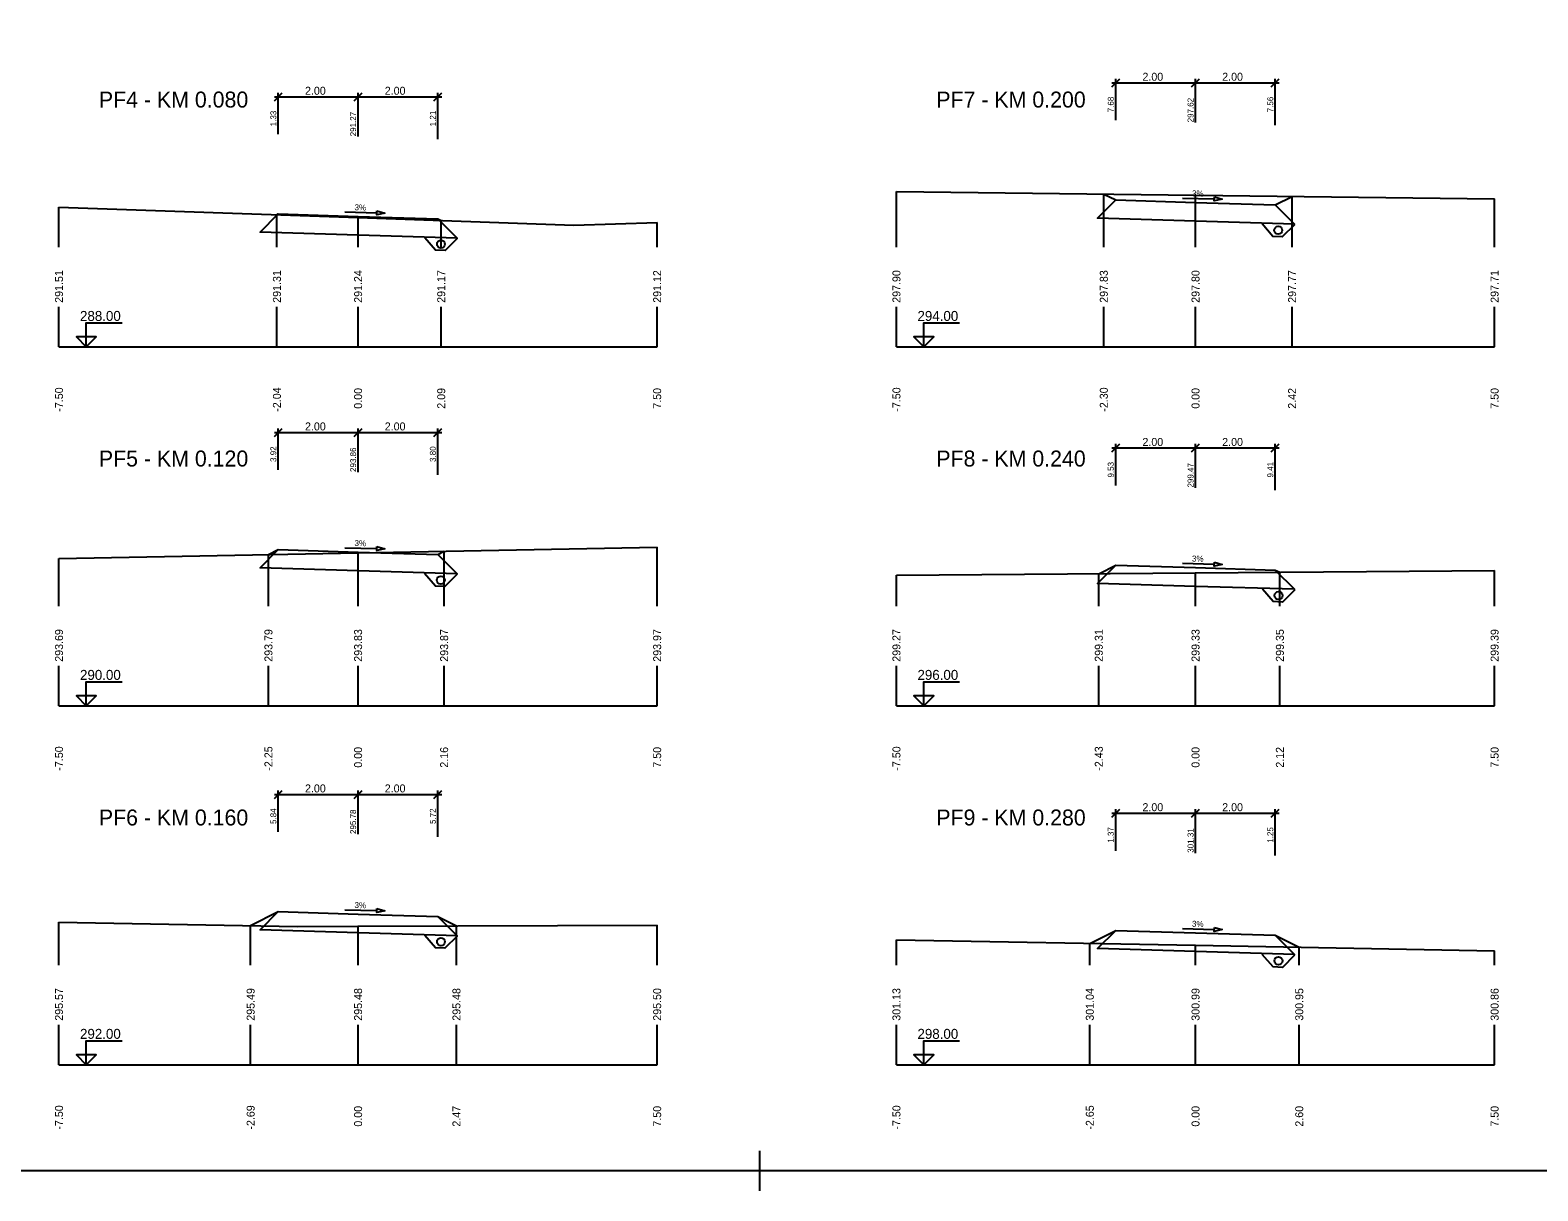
# Model space of a CAD drawing. Extents: x -9 to 2311, y -2 to 597.
# Drawn here: x 232.8 to 610.8, y -1.6 to 289.4 of the extents above; entities that cross this region are included whole.
import ezdxf

# ---------------------------------------------------------------- set-up
doc = ezdxf.new("R2010")
doc.units = 0
for name, color, linetype in [('KOTA', 7, 'Continuous'), ('KOTA_DELKY', 7, 'Continuous'), ('KOTA_DELKY_CONT', 7, 'Continuous'), ('NS_TELESO_VOZOVKY', 7, 'Continuous'), ('NS_V_PF', 7, 'Continuous'), ('REZY_PF_PUVODNI', 7, 'Continuous'), ('SESTAVY_REZU_PF', 7, 'Continuous'), ('SKLON', 7, 'Continuous'), ('SVK', 7, 'Continuous')]:
    doc.layers.add(name, color=color, linetype=linetype)

msp = doc.modelspace()

# ---------------------------------------------------------------- linework, layer by layer
for p, q in [((415.65, 8.39), (415.65, -1.61)), ((415.65, 8.39), (415.65, -1.61)), ((415.65, 8.39), (415.65, -1.61)), ((415.65, 8.39), (415.65, -1.61)), ((420.65, 3.39), (410.65, 3.39)), ((420.65, 3.39), (410.65, 3.39)), ((420.65, 3.39), (410.65, 3.39)), ((420.65, 3.39), (410.65, 3.39))]:
    msp.add_line(p, q)
msp.add_lwpolyline([(-4.35, 597.39), (2305.65, 597.39), (2305.65, 3.39), (-4.35, 3.39)], close=True)
for points in [[(549.79, 240.63), (546.74, 237.6), (544.39, 237.7), (541.68, 240.83)], [(339.85, 237.16), (336.8, 234.13), (334.45, 234.23), (331.74, 237.36)], [(339.8, 152.94), (336.75, 149.9), (334.4, 150), (331.69, 153.14)], [(549.87, 149.06), (546.82, 146.02), (544.47, 146.12), (541.76, 149.25)], [(339.85, 62.25), (336.79, 59.21), (334.45, 59.31), (331.74, 62.45)], [(549.85, 57.47), (546.8, 54.43), (544.45, 54.53), (541.74, 57.67)]]:
    msp.add_lwpolyline(points)
for centre in [(545.73, 239.23), (335.79, 235.76), (335.74, 151.53), (545.81, 147.65), (335.79, 60.84), (545.79, 56.07)]:
    msp.add_circle(centre, 1)
at = {"layer": 'KOTA'}
for points in [[(246.85, 212.5), (244.35, 212.5), (246.85, 210), (246.85, 216), (255.85, 216)], [(456.85, 212.5), (454.35, 212.5), (456.85, 210), (456.85, 216), (465.85, 216)], [(246.85, 210), (249.35, 212.5), (246.85, 212.5)], [(456.85, 210), (459.35, 212.5), (456.85, 212.5)], [(246.85, 122.5), (244.35, 122.5), (246.85, 120), (246.85, 126), (255.85, 126)], [(456.85, 122.5), (454.35, 122.5), (456.85, 120), (456.85, 126), (465.85, 126)], [(246.85, 120), (249.35, 122.5), (246.85, 122.5)], [(456.85, 120), (459.35, 122.5), (456.85, 122.5)], [(246.85, 32.5), (244.35, 32.5), (246.85, 30), (246.85, 36), (255.85, 36)], [(456.85, 32.5), (454.35, 32.5), (456.85, 30), (456.85, 36), (465.85, 36)], [(246.85, 30), (249.35, 32.5), (246.85, 32.5)], [(456.85, 30), (459.35, 32.5), (456.85, 32.5)]]:
    msp.add_lwpolyline(points, dxfattribs=at)
at = {"layer": 'KOTA_DELKY'}
for points in [[(504, 275.22), (506, 277.22)], [(504, 276.22), (526, 276.22)], [(505, 266.82), (505, 277.22)], [(524, 275.22), (526, 277.22)], [(524, 275.22), (526, 277.22)], [(524, 276.22), (546, 276.22)], [(525, 266.22), (525, 277.22)], [(525, 266.22), (525, 277.22)], [(544, 275.22), (546, 277.22)], [(545, 265.62), (545, 277.22)], [(294, 271.71), (296, 273.71)], [(294, 272.71), (316, 272.71)], [(295, 263.31), (295, 273.71)], [(314, 271.71), (316, 273.71)], [(314, 271.71), (316, 273.71)], [(314, 272.71), (336, 272.71)], [(315, 262.71), (315, 273.71)], [(315, 262.71), (315, 273.71)], [(334, 271.71), (336, 273.71)], [(335, 262.11), (335, 273.71)], [(294, 187.55), (296, 189.55)], [(295, 179.15), (295, 189.55)], [(314, 187.55), (316, 189.55)], [(314, 187.55), (316, 189.55)], [(315, 178.55), (315, 189.55)], [(315, 178.55), (315, 189.55)], [(334, 187.55), (336, 189.55)], [(335, 177.95), (335, 189.55)], [(294, 188.55), (316, 188.55)], [(314, 188.55), (336, 188.55)], [(504, 183.65), (506, 185.65)], [(505, 175.25), (505, 185.65)], [(524, 183.65), (526, 185.65)], [(524, 183.65), (526, 185.65)], [(525, 174.65), (525, 185.65)], [(525, 174.65), (525, 185.65)], [(544, 183.65), (546, 185.65)], [(545, 174.05), (545, 185.65)], [(504, 184.65), (526, 184.65)], [(524, 184.65), (546, 184.65)], [(294, 96.79), (296, 98.79)], [(295, 88.39), (295, 98.79)], [(314, 96.79), (316, 98.79)], [(314, 96.79), (316, 98.79)], [(315, 87.79), (315, 98.79)], [(315, 87.79), (315, 98.79)], [(334, 96.79), (336, 98.79)], [(335, 87.19), (335, 98.79)], [(294, 97.79), (316, 97.79)], [(314, 97.79), (336, 97.79)], [(504, 92.08), (506, 94.08)], [(504, 93.08), (526, 93.08)], [(505, 83.68), (505, 94.08)], [(524, 92.08), (526, 94.08)], [(524, 92.08), (526, 94.08)], [(524, 93.08), (546, 93.08)], [(525, 83.08), (525, 94.08)], [(525, 83.08), (525, 94.08)], [(544, 92.08), (546, 94.08)], [(545, 82.48), (545, 94.08)]]:
    msp.add_lwpolyline(points, dxfattribs=at)
at = {"layer": 'NS_TELESO_VOZOVKY'}
for points in [[(525, 246.22), (545, 245.62), (545, 245.62), (549.85, 240.77), (525, 241.52), (500.44, 242.25), (505, 246.82), (505, 246.82), (525, 246.22)], [(315, 242.71), (335, 242.11), (335, 242.11), (339.85, 237.26), (315, 238.01), (290.44, 238.75), (295, 243.31), (295, 243.31), (315, 242.71)], [(315, 158.55), (335, 157.95), (335, 157.95), (339.85, 153.11), (315, 153.85), (290.44, 154.59), (295, 159.15), (295, 159.15), (315, 158.55)], [(525, 154.65), (545, 154.05), (545, 154.05), (549.85, 149.21), (525, 149.95), (500.44, 150.69), (505, 155.25), (505, 155.25), (525, 154.65)], [(315, 67.79), (335, 67.19), (335, 67.19), (339.85, 62.34), (315, 63.09), (290.44, 63.82), (295, 68.39), (295, 68.39), (315, 67.79)], [(525, 63.08), (545, 62.48), (545, 62.48), (549.85, 57.64), (525, 58.38), (500.44, 59.12), (505, 63.68), (505, 63.68), (525, 63.08)]]:
    msp.add_lwpolyline(points, dxfattribs=at)
at = {"layer": 'NS_V_PF'}
for points in [[(502, 248.32), (505, 246.82), (505, 246.82), (525, 246.22), (545, 245.62), (545, 245.62), (549.21, 247.72)], [(294.65, 243.13), (295, 243.31), (295, 243.31), (315, 242.71), (335, 242.11), (335, 242.11), (335.85, 241.68)], [(292.52, 157.91), (295, 159.15), (295, 159.15), (315, 158.55), (335, 157.95), (335, 157.95), (336.58, 158.74)], [(500.74, 153.12), (505, 155.25), (505, 155.25), (525, 154.65), (545, 154.05), (545, 154.05), (546.15, 153.47)], [(288.06, 64.91), (295, 68.39), (295, 68.39), (315, 67.79), (335, 67.19), (335, 67.19), (339.67, 64.85)], [(498.49, 60.43), (505, 63.68), (505, 63.68), (525, 63.08), (545, 62.48), (545, 62.48), (551.01, 59.48)]]:
    msp.add_lwpolyline(points, dxfattribs=at)
at = {"layer": 'REZY_PF_PUVODNI'}
for points in [[(450, 248.97), (525, 248.03), (525, 248.03), (600, 247.08)], [(240, 245.05), (315, 242.41), (315, 242.41), (369.12, 240.51), (390, 241.16)], [(240, 156.92), (315, 158.33), (315, 158.33), (390, 159.74)], [(450, 152.73), (525, 153.31), (525, 153.31), (600, 153.89)], [(240, 65.75), (299.84, 64.71), (315, 64.76), (315, 64.76), (390, 65.02)], [(450, 61.3), (525, 59.95), (525, 59.95), (600, 58.59)]]:
    msp.add_lwpolyline(points, dxfattribs=at)
at = {"layer": 'SESTAVY_REZU_PF'}
for points in [[(240, 210), (390, 210)], [(450, 210), (600, 210)], [(240, 120), (390, 120)], [(450, 120), (600, 120)], [(240, 30), (390, 30)], [(450, 30), (600, 30)]]:
    msp.add_lwpolyline(points, dxfattribs=at)
at = {"layer": 'SKLON'}
for points in [[(521.71, 247.32), (529.71, 247.08)], [(529.73, 247.58), (531.71, 247.02), (529.7, 246.58), (529.73, 247.58)], [(311.71, 243.81), (319.71, 243.57)], [(319.73, 244.07), (321.71, 243.51), (319.7, 243.07), (319.73, 244.07)], [(311.71, 159.65), (319.71, 159.41)], [(319.73, 159.91), (321.71, 159.35), (319.7, 158.91), (319.73, 159.91)], [(521.71, 155.75), (529.71, 155.51)], [(529.73, 156.01), (531.71, 155.45), (529.7, 155.01), (529.73, 156.01)], [(311.71, 68.88), (319.71, 68.64)], [(319.73, 69.14), (321.71, 68.58), (319.7, 68.14), (319.73, 69.14)], [(529.73, 64.44), (531.71, 63.88), (529.7, 63.44), (529.73, 64.44)], [(521.71, 64.18), (529.71, 63.94)]]:
    msp.add_lwpolyline(points, dxfattribs=at)
at = {"layer": 'SVK'}
for points in [[(450, 235), (450, 248.97)], [(502, 235), (502, 248.32)], [(525, 235), (525, 248.03)], [(549.21, 235), (549.21, 247.72)], [(600, 235), (600, 247.08)], [(240, 235), (240, 245.05)], [(294.65, 235), (294.65, 243.13)], [(315, 235), (315, 242.41)], [(335.85, 235), (335.85, 241.68)], [(390, 235), (390, 241.16)], [(240, 210), (240, 220)], [(294.65, 210), (294.65, 220)], [(315, 210), (315, 220)], [(335.85, 210), (335.85, 220)], [(390, 210), (390, 220)], [(450, 210), (450, 220)], [(502, 210), (502, 220)], [(525, 210), (525, 220)], [(549.21, 210), (549.21, 220)], [(600, 210), (600, 220)], [(390, 145), (390, 159.74)], [(240, 145), (240, 156.92)], [(292.52, 145), (292.52, 157.91)], [(315, 145), (315, 158.33)], [(336.58, 145), (336.58, 158.74)], [(450, 145), (450, 152.73)], [(500.74, 145), (500.74, 153.12)], [(525, 145), (525, 153.31)], [(546.15, 145), (546.15, 153.47)], [(600, 145), (600, 153.89)], [(240, 120), (240, 130)], [(292.52, 120), (292.52, 130)], [(315, 120), (315, 130)], [(336.58, 120), (336.58, 130)], [(390, 120), (390, 130)], [(450, 120), (450, 130)], [(500.74, 120), (500.74, 130)], [(525, 120), (525, 130)], [(546.15, 120), (546.15, 130)], [(600, 120), (600, 130)], [(240, 55), (240, 65.75)], [(288.06, 55), (288.06, 64.91)], [(315, 55), (315, 64.76)], [(339.67, 55), (339.67, 64.85)], [(390, 55), (390, 65.02)], [(450, 55), (450, 61.3)], [(498.49, 55), (498.49, 60.43)], [(525, 55), (525, 59.95)], [(551.01, 55), (551.01, 59.48)], [(600, 55), (600, 58.59)], [(240, 30), (240, 40)], [(288.06, 30), (288.06, 40)], [(315, 30), (315, 40)], [(339.67, 30), (339.67, 40)], [(390, 30), (390, 40)], [(450, 30), (450, 40)], [(498.49, 30), (498.49, 40)], [(525, 30), (525, 40)], [(551.01, 30), (551.01, 40)], [(600, 30), (600, 40)]]:
    msp.add_lwpolyline(points, dxfattribs=at)

# ---------------------------------------------------------------- texts
at = {"layer": 'KOTA'}
for s, p in [('288.00', (245.27, 216.5)), ('294.00', (455.27, 216.5)), ('290.00', (245.27, 126.5)), ('296.00', (455.27, 126.5)), ('292.00', (245.27, 36.5)), ('298.00', (455.27, 36.5))]:
    msp.add_text(s, height=2.5, dxfattribs=at).set_placement(p)
at = {"layer": 'KOTA_DELKY'}
for p in [(511.69, 276.72), (531.69, 276.72), (301.69, 273.21), (321.69, 273.21), (301.69, 189.05), (321.69, 189.05), (511.69, 185.15), (531.69, 185.15), (301.69, 98.29), (321.69, 98.29), (511.69, 93.58), (531.69, 93.58)]:
    msp.add_text('2.00', height=2, dxfattribs=at).set_placement(p)
at = {"layer": 'KOTA_DELKY_CONT'}
for s, p in [('7.68', (504.5, 268.81)), ('297.62', (524.5, 266.29)), ('7.56', (544.5, 268.81)), ('1.33', (294.5, 265.3)), ('291.27', (314.5, 262.79)), ('1.21', (334.5, 265.3)), ('3.92', (294.5, 181.14)), ('293.86', (314.5, 178.63)), ('3.80', (334.5, 181.14)), ('9.53', (504.5, 177.24)), ('299.47', (524.5, 174.73)), ('9.41', (544.5, 177.24)), ('5.84', (294.5, 90.37)), ('295.78', (314.5, 87.86)), ('5.72', (334.5, 90.37)), ('1.37', (504.5, 85.67)), ('301.31', (524.5, 83.16)), ('1.25', (544.5, 85.67))]:
    msp.add_text(s, height=1.5, rotation=90, dxfattribs=at).set_placement(p)
at = {"layer": 'SESTAVY_REZU_PF'}
for s, p in [('PF4 - KM 0.080', (250, 270)), ('PF7 - KM 0.200', (460, 270)), ('PF5 - KM 0.120', (250, 180)), ('PF8 - KM 0.240', (460, 180)), ('PF6 - KM 0.160', (250, 90)), ('PF9 - KM 0.280', (460, 90))]:
    msp.add_text(s, height=4, dxfattribs=at).set_placement(p)
at = {"layer": 'SKLON'}
for p in [(314.09, 244.24), (524.09, 247.75), (314.09, 160.08), (524.09, 156.18), (314.09, 69.31), (524.09, 64.61)]:
    msp.add_text('3%', height=1.5, rotation=358.2816, dxfattribs=at).set_placement(p)
at = {"layer": 'SVK'}
for s, p in [(' 291.51', (241, 220.3)), (' 291.31', (295.65, 220.3)), (' 291.24', (316, 220.3)), (' 291.17', (336.85, 220.3)), (' 291.12', (391, 220.3)), (' 297.90', (451, 220.3)), (' 297.83', (503, 220.3)), (' 297.80', (526, 220.3)), (' 297.77', (550.21, 220.3)), (' 297.71', (601, 220.3)), (' -7.50', (241, 193)), (' -2.04', (295.65, 193)), ('  0.00', (316, 193)), ('  2.09', (336.85, 193)), ('  7.50', (391, 193)), (' -7.50', (451, 193)), (' -2.30', (503, 193)), ('  0.00', (526, 193)), ('  2.42', (550.21, 193)), ('  7.50', (601, 193)), (' 293.69', (241, 130.3)), (' 293.79', (293.52, 130.3)), (' 293.83', (316, 130.3)), (' 293.87', (337.58, 130.3)), (' 293.97', (391, 130.3)), (' 299.27', (451, 130.3)), (' 299.31', (501.74, 130.3)), (' 299.33', (526, 130.3)), (' 299.35', (547.15, 130.3)), (' 299.39', (601, 130.3)), (' -7.50', (241, 103)), (' -2.25', (293.52, 103)), (' -7.50', (451, 103)), (' -2.43', (501.74, 103)), ('  0.00', (316, 103)), ('  2.16', (337.58, 103)), ('  7.50', (391, 103)), ('  0.00', (526, 103)), ('  2.12', (547.15, 103)), ('  7.50', (601, 103)), (' 295.57', (241, 40.3)), (' 295.49', (289.06, 40.3)), (' 295.48', (316, 40.3)), (' 295.48', (340.67, 40.3)), (' 295.50', (391, 40.3)), (' 301.13', (451, 40.3)), (' 301.04', (499.49, 40.3)), (' 300.99', (526, 40.3)), (' 300.95', (552.01, 40.3)), (' 300.86', (601, 40.3)), (' -7.50', (241, 13)), (' -2.69', (289.06, 13)), ('  0.00', (316, 13)), ('  2.47', (340.67, 13)), ('  7.50', (391, 13)), (' -7.50', (451, 13)), (' -2.65', (499.49, 13)), ('  0.00', (526, 13)), ('  2.60', (552.01, 13)), ('  7.50', (601, 13))]:
    msp.add_text(s, height=2, rotation=90, dxfattribs=at).set_placement(p)

doc.saveas('drawing.dxf')
